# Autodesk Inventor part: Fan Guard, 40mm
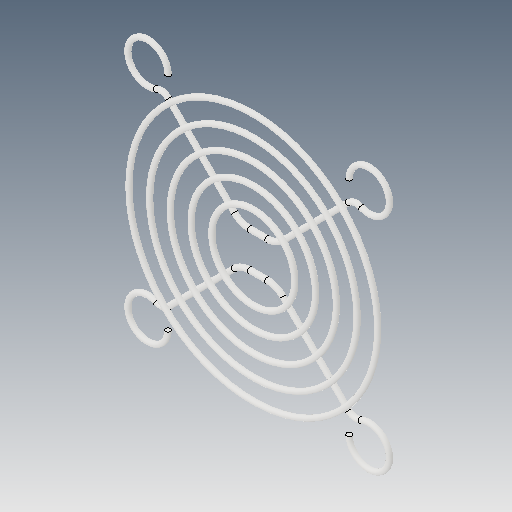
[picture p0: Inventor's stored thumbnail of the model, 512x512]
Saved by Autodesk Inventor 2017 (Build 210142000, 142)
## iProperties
Created: 2005-12
Part Number: Fan Guard, 40mm
Material: Generic
Document SubType Name: Modeling
Designer: DanielSeverino
Density: 1 g/cm^3
Appearance: Default
Author: DanielSeverino
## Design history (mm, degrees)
feature "Solid1"
feature "Solid1:1"
feature "Solid1:2"
feature "Solid1:3"
feature "Solid1:4"
feature "Solid1:5"
feature "Solid1:6"
body "Solid2"
body "Solid3"
body "Solid4"
body "Solid5"
body "Solid6"
body "Solid7"
body "Solid8"
